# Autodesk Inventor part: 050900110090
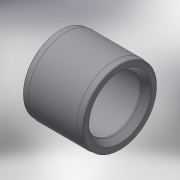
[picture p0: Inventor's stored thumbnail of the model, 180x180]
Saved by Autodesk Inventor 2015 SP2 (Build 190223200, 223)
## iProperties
Created: 2017-11
Part Number: 050900110090
Material: Generic
Description: PLASSON BUSHING-CEMENT PVC 110-90
Document SubType Name: Modeling
Designer: KIM
Density: 1 g/cm^3
Appearance: Default
Author: KIM
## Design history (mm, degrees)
derived "050900.ipt"
feature "Solid1::050900.ipt"
tag "TaggingFeature1"
body "Solid1"
other parameters: "d2" = 51, "d3" = 61, "d7" = 6.1, "d11" = 6.1, "d12" = 1.1, "d14" = 1.1, "d15" = 6.1, "d17" = 1.1, "d18" = 1.1, "d19" = 80.1, "d20" = 2, "d21" = 8.97, "L_" = 61, "l_" = 51, "z_" = 2
